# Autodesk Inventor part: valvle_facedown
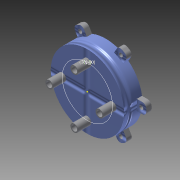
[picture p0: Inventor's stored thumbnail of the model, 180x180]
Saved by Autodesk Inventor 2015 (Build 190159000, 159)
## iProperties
Created: 2017-05
Part Number: valvle_facedown
Material: Generic
Document SubType Name: Modeling
Designer: mcalderon
Density: 1 g/cm^3
Appearance: Default
Author: mcalderon
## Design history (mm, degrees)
sketch "Sketch1"
  geometry: L1 (-25, 25)-(25, 25); L2 (25, 25)-(25, -25); L3 (25, -25)-(-25, -25); L4 (-25, -25)-(-25, 25); L5 (-25, 25)-(25, -25); L6 (25, 25)-(-25, -25); C1 r 25 at (0, 0); C2 r 28 at (0, 0); 1 further point
  constraints: 12 end point, 4 midpoint, 2 centre point, 2 parallel, 1 coincident, 1 horizontal, 1 perpendicular
  dimensions: "d0" = 50 diameter of C1; "d1" = 50 distance of L2.end L3.end; "d2" = 50 distance of L1.end L2.end; "d3" = 56 diameter of C2
extrude "Extrusion1" new body sketch "Sketch1" distance "d4" = 10; taper "d5" = 0 deg
sketch "Sketch2"
  geometry: L1 (-25, 0)-(-35, 0); L2 (-35, 0)-(-35, 1); L3 (-32, 4)-(-25, 4); L4 (-25, 4)-(-25, 0); L5 (-35, 0)-(-35, -1); L6 (-32, -4)-(-25, -4); L7 (-29.247, -4)-(-29.247, 4); L8 (-25, -4)-(-25, 0); L9 (-11.159, -27.329)-(-18.088, -23.329); L10 (-12.536, -29.713)-(-9.036, -23.651); L11 (-9.036, -23.651)-(-12.5, -21.651); L12 (-15.964, -19.651)-(-12.5, -21.651); L13 (-19.464, -25.713)-(-15.964, -19.651); L14 (-17.5, -30.311)-(-18.366, -29.811); L15 (-17.5, -30.311)-(-16.634, -30.811); L16 (18.088, -23.329)-(11.159, -27.329); L17 (19.464, -25.713)-(15.964, -19.651); L18 (15.964, -19.651)-(12.5, -21.651); L19 (9.036, -23.651)-(12.5, -21.651); L20 (12.536, -29.713)-(9.036, -23.651); L21 (17.5, -30.311)-(16.634, -30.811); L22 (17.5, -30.311)-(18.366, -29.811); L23 (29.247, 4)-(29.247, -4); L24 (32, 4)-(25, 4); L25 (25, 4)-(25, 0); L26 (25, -4)-(25, 0); L27 (32, -4)-(25, -4); L28 (35, 0)-(35, -1); L29 (35, 0)-(35, 1); L30 (11.159, 27.329)-(18.088, 23.329); L31 (12.536, 29.713)-(9.036, 23.651); L32 (9.036, 23.651)-(12.5, 21.651); L33 (15.964, 19.651)-(12.5, 21.651); L34 (19.464, 25.713)-(15.964, 19.651); L35 (17.5, 30.311)-(18.366, 29.811); L36 (17.5, 30.311)-(16.634, 30.811); L37 (-18.088, 23.329)-(-11.159, 27.329); L38 (-19.464, 25.713)-(-15.964, 19.651); L39 (-15.964, 19.651)-(-12.5, 21.651); L40 (-9.036, 23.651)-(-12.5, 21.651); L41 (-12.536, 29.713)-(-9.036, 23.651); L42 (-17.5, 30.311)-(-16.634, 30.811); L43 (-17.5, 30.311)-(-18.366, 29.811); C1 r 1.5 at (-31.163, 0); C2 r 1.5 at (-15.582, -26.988); C3 r 1.5 at (15.582, -26.988); C4 r 1.5 at (31.163, 0); C5 r 1.5 at (15.582, 26.988); C6 r 1.5 at (-15.582, 26.988); A1 r 3 centre (-32, -1) between (-35, -1) and (-32, -4); A2 r 3 centre (-32, 1) between (-32, 4) and (-35, 1); A3 r 3 centre (-16.866, -27.213) between (-19.464, -25.713) and (-18.366, -29.811); A4 r 3 centre (-15.134, -28.213) between (-16.634, -30.811) and (-12.536, -29.713); A5 r 3 centre (15.134, -28.213) between (12.536, -29.713) and (16.634, -30.811); A6 r 3 centre (16.866, -27.213) between (18.366, -29.811) and (19.464, -25.713); A7 r 3 centre (32, -1) between (32, -4) and (35, -1); A8 r 3 centre (32, 1) between (35, 1) and (32, 4); A9 r 3 centre (16.866, 27.213) between (19.464, 25.713) and (18.366, 29.811); A10 r 3 centre (15.134, 28.213) between (16.634, 30.811) and (12.536, 29.713); A11 r 3 centre (-15.134, 28.213) between (-12.536, 29.713) and (-16.634, 30.811); A12 r 3 centre (-16.866, 27.213) between (-18.366, 29.811) and (-19.464, 25.713); 14 further points
  constraints: 86 end point, 37 point on line, 24 point on circle, 18 centre point, 4 tangent, 3 vertical, 2 parallel, 2 symmetric about line, 1 equal radius, 1 horizontal, 1 horizontal alignment, 1 perpendicular, 152 other
  dimensions: "d6" = 10 distance of point (-35, 4) L3.end; "d7" = 4 distance of L1.end point (-35, 4); "d9" = 3 radius of A1; "d10" = 3 diameter of C1; "d13" = 360 deg dimension on point (0, 0) L7.start (derived)
extrude "Extrusion2" join sketch "Sketch2" distance "d15" = 4; taper "d16" = 0 deg
sketch "Sketch3"
  geometry: C1 r 28 at (0, 0); 1 further point
  constraints: 1 centre point, 1 coincident
  dimensions: "d17" = 56 diameter of C1
extrude "Extrusion3" join sketch "Sketch3" distance "d18" = 4; taper "d19" = 0 deg
sketch "Sketch7"
  geometry: C1 r 2.15 at (0, 19.21); C2 r 2.15 at (-19.21, 0); C3 r 2.15 at (0, -19.21); C4 r 2.15 at (19.21, 0); 1 further point
  constraints: 4 centre point, 9 other
  dimensions: "d32" = 4.3 diameter of C1; "d35" = 360 deg dimension on point (0, 0) C1.centre (derived)
hole "Hole1" sketch "Sketch7" at (0, 19.21), (-19.21, 0), (0, -19.21), (19.21, 0) diameter "d37" = 4.3; stored, may be unused: countersink angle "d41" = 90 deg, drill point angle "d43" = 0 deg; dims "d38" = 6, "d39" = 4, "d40" = 2, "d42" = 4
sketch "Sketch8"
  geometry: C1 r 2.15 at (0, 19.21) reference; C2 r 2.15 at (0, 19.21); C3 r 3 at (0, 19.21); C4 r 3 at (-19.21, 0); C5 r 2.15 at (-19.21, 0); C6 r 3 at (0, -19.21); C7 r 2.15 at (0, -19.21); C8 r 3 at (19.21, 0); C9 r 2.15 at (19.21, 0); 1 further point
  constraints: 8 centre point, 5 coincident, 17 other
  dimensions: "d44" = 4.3 diameter of C2; "d45" = 6 diameter of C3; "d48" = 360 deg dimension on point (0, 0) C3.centre (derived)
extrude "Extrusion7" join sketch "Sketch8" distance "d50" = 10; taper "d51" = 0 deg
sketch "Sketch9"
  geometry: C1 r 2.15 at (0, 19.21) reference; C2 r 2.15 at (0, 19.21); C3 r 2.5 at (0, 19.21); C4 r 2.5 at (0, 19.21); C5 r 2.15 at (-19.21, 0); C6 r 2.5 at (-19.21, 0); C7 r 2.15 at (0, -19.21); C8 r 2.5 at (0, -19.21); C9 r 2.15 at (19.21, 0); C10 r 2.5 at (19.21, 0); 1 further point
  constraints: 9 centre point, 3 coincident, 17 other
  dimensions: "d52" = 4.3 diameter of C2; "d54" = 5 diameter of C4; "d57" = 360 deg dimension on point (0, 0) C2.centre (derived)
body "Solid1"
